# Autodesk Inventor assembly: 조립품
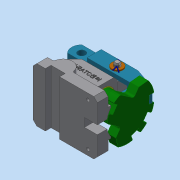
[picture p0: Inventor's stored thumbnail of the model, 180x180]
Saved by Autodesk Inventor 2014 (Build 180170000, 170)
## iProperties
Created: 2022-08
Part Number: 조립품
Document SubType Name: Assembly
Designer: dg
Author: dg
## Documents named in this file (8)
- C:\Users\dg\Desktop\720806V1017\조립품.iam
- C:\Users\dg\Desktop\720806V1017\본체.ipt
- C:\Users\dg\Desktop\720806V1017\부시.ipt
- C:\Users\dg\Desktop\720806V1017\분할대.ipt
- C:\Users\dg\Desktop\720806V1017\분할축.ipt
- C:\Users\dg\Desktop\720806V1017\분할핀.ipt
- C:\Users\dg\Desktop\720806V1017\와셔.ipt
- C:\Users\dg\Desktop\720806V1017\클레비스핀.ipt
